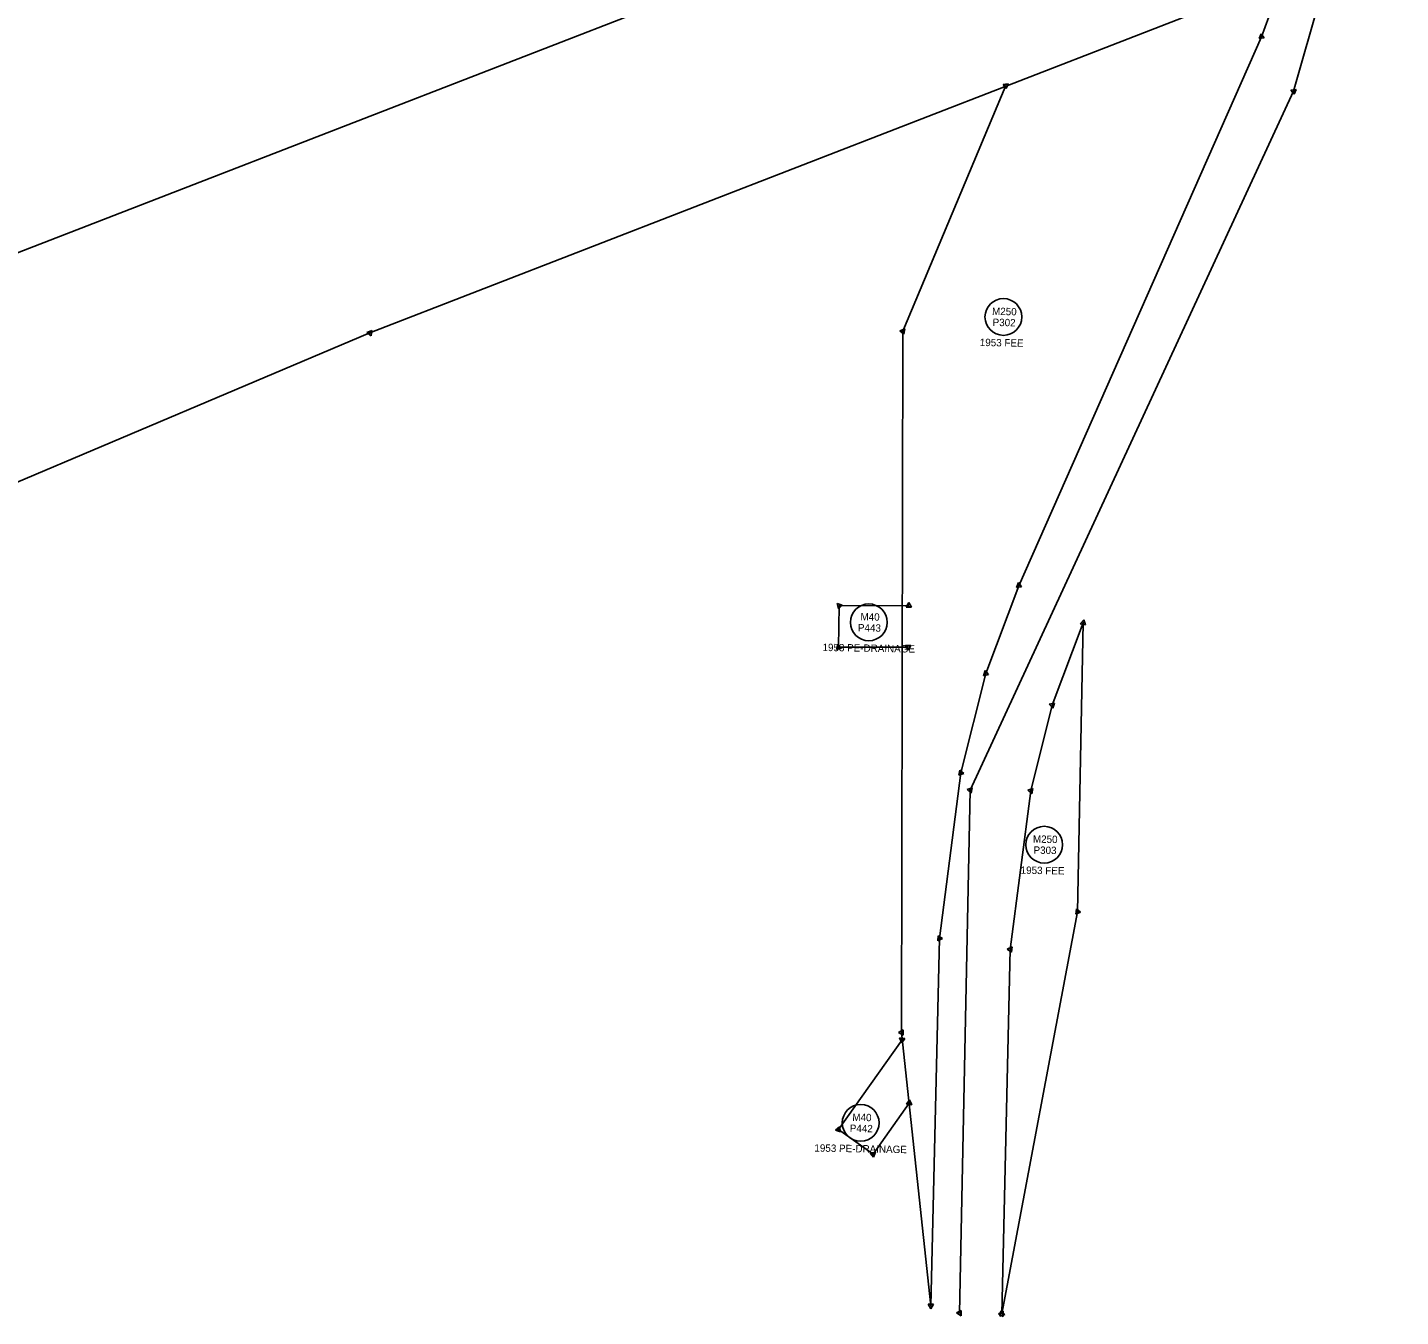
# Model space of a CAD drawing. Extents: x 325029 to 414988, y 1517527 to 1550420.
# Drawn here: x 389678 to 390657, y 1519021 to 1519941 of the extents above; entities that cross this region are included whole.
import ezdxf

# ---------------------------------------------------------------- set-up
doc = ezdxf.new("R2010")
doc.units = 0
for name, color, linetype in [('Level 56', 7, 'Continuous'), ('MEE', 7, 'Continuous'), ('MHB', 7, 'Continuous'), ('MHBWOA', 7, 'Continuous'), ('MRBL1', 7, 'Continuous'), ('MRBL2', 7, 'Continuous')]:
    doc.layers.add(name, color=color, linetype=linetype)

msp = doc.modelspace()

# ---------------------------------------------------------------- linework, layer by layer
at = {"layer": 'Level 56'}
for centre in [(390373.81, 1519734.26), (390277.85, 1519516.49), (390402.95, 1519357.93), (390272.06, 1519159.53)]:
    msp.add_circle(centre, 13.12, dxfattribs=at)
at = {"layer": 'MEE'}
for p, q in [((390256.29, 1519498.73), (390256.74, 1519528.28)), ((390256.74, 1519528.28), (390306.39, 1519528.44)), ((390305.95, 1519498.9), (390256.29, 1519498.73)), ((390256.25, 1519154.74), (390301.56, 1519218.84)), ((390306.65, 1519173.72), (390280.91, 1519137.24)), ((390280.91, 1519137.24), (390256.25, 1519154.74))]:
    msp.add_line(p, q, dxfattribs=at)
for points in [[(390256.16, 1519526.17), (390255.2, 1519529.83)], [(390255.2, 1519529.83), (390258.85, 1519528.83)], [(390258.85, 1519528.83), (390256.16, 1519526.17)], [(390304.51, 1519527.34), (390306.39, 1519530.62)], [(390308.29, 1519527.35), (390304.51, 1519527.34)], [(390306.39, 1519530.62), (390308.29, 1519527.35)], [(390254.74, 1519497.2), (390255.74, 1519500.85)], [(390258.39, 1519498.16), (390254.74, 1519497.2)], [(390255.74, 1519500.85), (390258.39, 1519498.16)], [(390304.05, 1519499.98), (390307.83, 1519500)], [(390305.95, 1519496.72), (390304.05, 1519499.98)], [(390307.83, 1519500), (390305.95, 1519496.72)], [(390301.36, 1519216.66), (390299.78, 1519220.09)], [(390299.78, 1519220.09), (390303.54, 1519219.75)], [(390303.54, 1519219.75), (390301.36, 1519216.66)], [(390304.66, 1519172.81), (390306.84, 1519175.9)], [(390308.43, 1519172.47), (390304.66, 1519172.81)], [(390306.84, 1519175.9), (390308.43, 1519172.47)], [(390254.11, 1519154.37), (390257.01, 1519156.78)], [(390257.65, 1519153.06), (390254.11, 1519154.37)], [(390257.01, 1519156.78), (390257.65, 1519153.06)], [(390278.86, 1519138), (390282.58, 1519138.63)], [(390281.27, 1519135.09), (390278.86, 1519138)], [(390282.58, 1519138.63), (390281.27, 1519135.09)]]:
    msp.add_lwpolyline(points, dxfattribs=at)
for centre, radius in [((390256.74, 1519528.28), 0.227), ((390306.4, 1519528.44), 1.09), ((390256.29, 1519498.73), 0.227), ((390305.94, 1519498.9), 1.09), ((390301.56, 1519218.84), 1.09), ((390306.65, 1519173.72), 1.09), ((390256.25, 1519154.74), 0.227), ((390280.91, 1519137.24), 0.227)]:
    msp.add_circle(centre, radius, dxfattribs=at)
at = {"layer": 'MHB'}
for p, q in [((390572.93, 1519975.42), (390557.82, 1519934.1)), ((390557.82, 1519934.1), (390384.8, 1519542.63)), ((390302.11, 1519724.04), (390375.61, 1519899.25)), ((390301.29, 1519224.04), (390302.11, 1519724.04)), ((390384.8, 1519542.63), (390361.24, 1519479.91)), ((390408.64, 1519457.46), (390430.7, 1519516.1)), ((390430.7, 1519516.1), (390426.74, 1519310.14)), ((390361.24, 1519479.91), (390343.46, 1519409.1)), ((390393.3, 1519396.36), (390408.64, 1519457.46)), ((390343.46, 1519409.1), (390328.25, 1519291.08)), ((390378.73, 1519283.29), (390393.3, 1519396.36)), ((390426.74, 1519310.14), (390372.63, 1519023.36)), ((390328.25, 1519291.08), (390322.11, 1519029.15)), ((390372.63, 1519023.36), (390378.73, 1519283.29)), ((390322.11, 1519029.15), (390301.29, 1519224.04))]:
    msp.add_line(p, q, dxfattribs=at)
for points in [[(390556.1, 1519932.75), (390557.51, 1519936.26)], [(390557.51, 1519936.26), (390559.84, 1519933.28)], [(390559.84, 1519933.28), (390556.1, 1519932.75)], [(390373.6, 1519900.09), (390377.35, 1519900.57)], [(390375.89, 1519897.08), (390373.6, 1519900.09)], [(390377.35, 1519900.57), (390375.89, 1519897.08)], [(390299.97, 1519724.47), (390303.55, 1519725.68)], [(390302.8, 1519721.97), (390299.97, 1519724.47)], [(390303.55, 1519725.68), (390302.8, 1519721.97)], [(390383.08, 1519541.29), (390384.5, 1519544.79)], [(390384.5, 1519544.79), (390386.82, 1519541.8)], [(390386.82, 1519541.8), (390383.08, 1519541.29)], [(390428.64, 1519515.38), (390431.11, 1519518.24)], [(390432.35, 1519514.67), (390428.64, 1519515.38)], [(390431.11, 1519518.24), (390432.35, 1519514.67)], [(390359.63, 1519478.43), (390360.76, 1519482.04)], [(390363.31, 1519479.26), (390359.63, 1519478.43)], [(390360.76, 1519482.04), (390363.31, 1519479.26)], [(390406.56, 1519458.11), (390410.25, 1519458.94)], [(390409.12, 1519455.33), (390406.56, 1519458.11)], [(390410.25, 1519458.94), (390409.12, 1519455.33)], [(390342.03, 1519407.45), (390342.74, 1519411.16)], [(390345.6, 1519408.7), (390342.03, 1519407.45)], [(390342.74, 1519411.16), (390345.6, 1519408.7)], [(390391.16, 1519396.76), (390394.72, 1519398.01)], [(390394.72, 1519398.01), (390394.02, 1519394.3)], [(390394.02, 1519394.3), (390391.16, 1519396.76)], [(390425.46, 1519308.37), (390425.85, 1519312.13)], [(390428.91, 1519309.91), (390425.46, 1519308.37)], [(390425.85, 1519312.13), (390428.91, 1519309.91)], [(390327.02, 1519289.28), (390327.3, 1519293.05)], [(390330.42, 1519290.92), (390327.02, 1519289.28)], [(390327.3, 1519293.05), (390330.42, 1519290.92)], [(390376.55, 1519283.46), (390379.96, 1519285.09)], [(390379.67, 1519281.33), (390376.55, 1519283.46)], [(390379.96, 1519285.09), (390379.67, 1519281.33)], [(390299.12, 1519223.93), (390302.28, 1519225.99)], [(390302.48, 1519222.21), (390299.12, 1519223.93)], [(390302.28, 1519225.99), (390302.48, 1519222.21)], [(390320.17, 1519030.17), (390323.95, 1519030.32)], [(390322.2, 1519026.98), (390320.17, 1519030.17)], [(390323.95, 1519030.32), (390322.2, 1519026.98)], [(390370.45, 1519023.41), (390373.77, 1519025.23)], [(390373.68, 1519021.45), (390370.45, 1519023.41)], [(390371.21, 1519021.71), (390371.91, 1519025.42)], [(390374.77, 1519022.96), (390371.21, 1519021.71)], [(390371.91, 1519025.42), (390374.77, 1519022.96)], [(390373.77, 1519025.23), (390373.68, 1519021.45)]]:
    msp.add_lwpolyline(points, dxfattribs=at)
for centre, radius in [((390557.82, 1519934.1), 0.227), ((390375.61, 1519899.25), 1.09), ((390302.11, 1519724.04), 0.227), ((390384.8, 1519542.63), 0.227), ((390430.7, 1519516.1), 0.227), ((390361.24, 1519479.91), 0.227), ((390408.64, 1519457.46), 0.227), ((390343.46, 1519409.1), 0.227), ((390393.3, 1519396.36), 0.227), ((390426.74, 1519310.14), 0.227), ((390328.25, 1519291.08), 0.227), ((390378.73, 1519283.29), 0.227), ((390301.29, 1519224.04), 0.227), ((390322.11, 1519029.15), 0.227), ((390372.63, 1519023.37), 1.09), ((390372.63, 1519023.36), 1.09)]:
    msp.add_circle(centre, radius, dxfattribs=at)
at = {"layer": 'MHBWOA'}
for p, q in [((390572.93, 1519975.42), (389922.2, 1519722.93)), ((389922.2, 1519722.93), (389461.32, 1519527.65))]:
    msp.add_line(p, q, dxfattribs=at)
for points in [[(389920.04, 1519723.23), (389923.54, 1519724.66)], [(389923.02, 1519720.91), (389920.04, 1519723.23)], [(389923.54, 1519724.66), (389923.02, 1519720.91)]]:
    msp.add_lwpolyline(points, dxfattribs=at)
msp.add_circle((389922.2, 1519722.93), 0.227, dxfattribs=at)
at = {"layer": 'MRBL1'}
msp.add_line((389439.7, 1519690.25), (390656.97, 1520162.48), dxfattribs=at)
at = {"layer": 'MRBL2'}
for p, q in [((390580.76, 1519895.17), (390656.97, 1520162.48)), ((390350.15, 1519396.78), (390580.76, 1519895.17)), ((390342.64, 1519023.97), (390350.15, 1519396.78))]:
    msp.add_line(p, q, dxfattribs=at)
for points in [[(390578.71, 1519895.93), (390582.44, 1519896.56)], [(390581.12, 1519893.02), (390578.71, 1519895.93)], [(390582.44, 1519896.56), (390581.12, 1519893.02)], [(390348.03, 1519397.27), (390351.64, 1519398.38)], [(390351.64, 1519398.38), (390350.79, 1519394.7)], [(390350.79, 1519394.7), (390348.03, 1519397.27)], [(390340.46, 1519024.01), (390343.77, 1519025.84)], [(390343.77, 1519025.84), (390343.69, 1519022.06)], [(390343.69, 1519022.06), (390340.46, 1519024.01)]]:
    msp.add_lwpolyline(points, dxfattribs=at)
for centre, radius in [((390580.76, 1519895.17), 0.227), ((390350.15, 1519396.78), 0.227), ((390342.64, 1519023.97), 1.09)]:
    msp.add_circle(centre, radius, dxfattribs=at)

# ---------------------------------------------------------------- texts
at = {"layer": 'Level 56'}
for s, height, p in [('M250', 5.249, (390365.7, 1519735.72)), ('P302', 5.249, (390366.11, 1519727.84)), ('1953 FEE', 5.249, (390356.96, 1519713.55)), ('P443', 5.249, (390270.08, 1519510.07)), ('M40', 5.249, (390271.9, 1519517.91)), ('1953 PE-DRAINAGE', 5.2493, (390244.83, 1519496.07)), ('M250', 5.249, (390394.84, 1519359.39)), ('P303', 5.249, (390395.27, 1519351.51)), ('1953 FEE', 5.249, (390386.1, 1519337.22)), ('M40', 5.249, (390266.1, 1519160.95)), ('P442', 5.249, (390264.27, 1519153.11)), ('1953 PE-DRAINAGE', 5.2493, (390239.04, 1519139.1))]:
    msp.add_text(s, height=height, rotation=358.97522, dxfattribs=at).set_placement(p)

doc.saveas('drawing.dxf')
